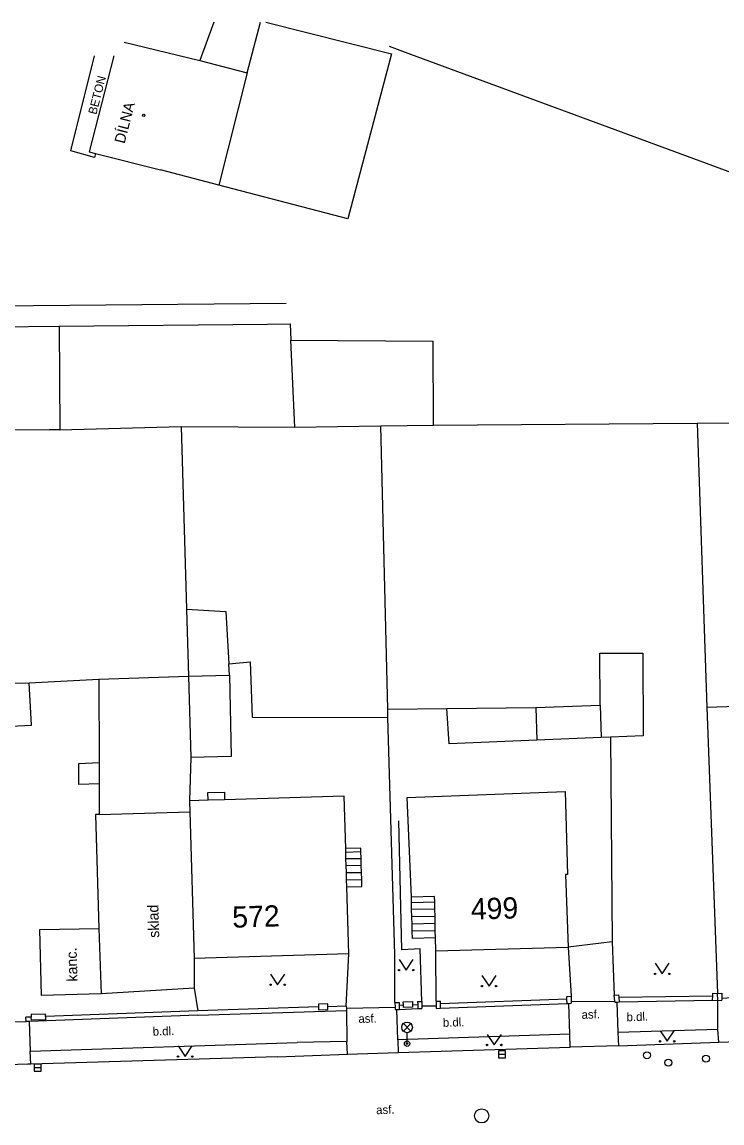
# Model space of a CAD drawing. Extents: x -642282 to -641982, y -1041678 to -1041427.
# Drawn here: x -642103.8 to -642054.4, y -1041504.2 to -1041426.5 of the extents above; entities that cross this region are included whole.
import ezdxf

# ---------------------------------------------------------------- set-up
doc = ezdxf.new("R2010")
doc.units = 0
for name, color, linetype in [('Budovy', 7, 'Continuous'), ('Ploty', 7, 'Continuous'), ('Popis objektů', 7, 'Continuous'), ('Popis povrchů', 7, 'Continuous'), ('Popis ČP_ ČE', 7, 'Continuous'), ('Pris-HUP', 7, 'Continuous'), ('Rozhraní ploch 1', 7, 'Continuous'), ('Rozhraní ploch 2', 7, 'Continuous'), ('Vstup na pozemky', 7, 'Continuous'), ('Znaky doprava', 7, 'Continuous'), ('Znaky kanalizace', 7, 'Continuous'), ('Znaky voda', 7, 'Continuous'), ('Značky KM', 7, 'Continuous'), ('Značky předmětů', 7, 'Continuous')]:
    doc.layers.add(name, color=color, linetype=linetype)

msp = doc.modelspace()

# ---------------------------------------------------------------- linework, layer by layer
at = {"layer": 'Budovy'}
for p, q in [((-642087.9, -1041430.08), (-642086.974, -1041426.503)), ((-642086.585, -1041426.503), (-642077.74, -1041428.76)), ((-642096.59, -1041427.92), (-642091.24, -1041429.22)), ((-642097.312, -1041428.899), (-642099.05, -1041435.67)), ((-642077.74, -1041428.76), (-642080.82, -1041440.39)), ((-642091.24, -1041429.22), (-642087.9, -1041430.08)), ((-642087.9, -1041430.08), (-642089.91, -1041438.01)), ((-642099.05, -1041435.67), (-642098.61, -1041435.79)), ((-642098.61, -1041435.79), (-642094.03, -1041436.93)), ((-642089.91, -1041438.01), (-642094.03, -1041436.93)), ((-642080.82, -1041440.39), (-642089.91, -1041438.01)), ((-642133.96, -1041448.34), (-642101.16, -1041447.981)), ((-642101.16, -1041447.981), (-642086.48, -1041447.82)), ((-642101.16, -1041447.981), (-642101.12, -1041455.28)), ((-642086.48, -1041447.82), (-642084.88, -1041447.8)), ((-642084.88, -1041447.8), (-642084.826, -1041448.968)), ((-642084.54, -1041455.11), (-642084.826, -1041448.968)), ((-642101.88, -1041455.29), (-642108.5, -1041455.35)), ((-642101.12, -1041455.28), (-642101.88, -1041455.29)), ((-642101.12, -1041455.28), (-642092.57, -1041455.06)), ((-642092.57, -1041455.06), (-642084.54, -1041455.11)), ((-642092.57, -1041455.06), (-642092.19, -1041467.96)), ((-642092.19, -1041467.96), (-642092.05, -1041472.69)), ((-642092.19, -1041467.96), (-642089.42, -1041468.11)), ((-642089.42, -1041468.11), (-642089.21, -1041471.8)), ((-642063.02, -1041474.73), (-642063.03, -1041471.05)), ((-642063.03, -1041471.05), (-642060, -1041471.05)), ((-642060, -1041471.05), (-642059.98, -1041476.89)), ((-642089.16, -1041472.6), (-642089.21, -1041471.8)), ((-642108.03, -1041473.19), (-642103.28, -1041473.15)), ((-642103.28, -1041473.15), (-642098.38, -1041472.9)), ((-642103.13, -1041476.14), (-642103.28, -1041473.15)), ((-642098.38, -1041472.9), (-642092.05, -1041472.69)), ((-642098.38, -1041472.9), (-642098.36, -1041478.78)), ((-642092.05, -1041472.69), (-642089.16, -1041472.6)), ((-642092.05, -1041472.69), (-642091.88, -1041478.41)), ((-642089.16, -1041472.6), (-642089.05, -1041478.36)), ((-642067.54, -1041474.88), (-642063.02, -1041474.73)), ((-642063.02, -1041474.73), (-642062.94, -1041477.01)), ((-642067.54, -1041474.88), (-642067.47, -1041477.2)), ((-642107.945, -1041476.383), (-642103.13, -1041476.14)), ((-642062.94, -1041477.01), (-642067.47, -1041477.2)), ((-642062.28, -1041476.98), (-642062.94, -1041477.01)), ((-642059.98, -1041476.89), (-642062.28, -1041476.98)), ((-642091.88, -1041478.41), (-642091.97, -1041481.48)), ((-642089.05, -1041478.36), (-642091.88, -1041478.41)), ((-642099.79, -1041478.85), (-642098.36, -1041478.78)), ((-642099.79, -1041480.33), (-642099.79, -1041478.85)), ((-642098.36, -1041478.78), (-642098.36, -1041480.28)), ((-642098.36, -1041480.28), (-642099.79, -1041480.33)), ((-642098.36, -1041480.28), (-642098.35, -1041482.45)), ((-642076.63, -1041481.25), (-642065.47, -1041480.82)), ((-642065.47, -1041480.82), (-642065.31, -1041486.68)), ((-642090.669, -1041481.442), (-642091.97, -1041481.48)), ((-642091.97, -1041481.48), (-642091.95, -1041482.26)), ((-642089.509, -1041481.408), (-642090.669, -1041481.442)), ((-642081.07, -1041481.16), (-642089.509, -1041481.408)), ((-642080.96, -1041484.85), (-642081.07, -1041481.16)), ((-642076.33, -1041488.27), (-642076.63, -1041481.25)), ((-642098.35, -1041482.45), (-642098.6, -1041482.45)), ((-642098.6, -1041482.45), (-642098.37, -1041490.49)), ((-642098.35, -1041482.45), (-642091.95, -1041482.26)), ((-642091.95, -1041482.26), (-642091.64, -1041492.62)), ((-642080.95, -1041485.11), (-642080.96, -1041484.85)), ((-642080.94, -1041485.54), (-642080.95, -1041485.11)), ((-642080.93, -1041486.04), (-642080.94, -1041485.54)), ((-642080.91, -1041486.55), (-642080.93, -1041486.04)), ((-642080.9, -1041487.06), (-642080.91, -1041486.55)), ((-642080.88, -1041487.56), (-642080.9, -1041487.06)), ((-642065.31, -1041486.68), (-642065.46, -1041486.69)), ((-642065.46, -1041486.69), (-642065.27, -1041491.82)), ((-642080.74, -1041492.29), (-642080.88, -1041487.56)), ((-642074.69, -1041488.23), (-642076.33, -1041488.27)), ((-642074.68, -1041488.64), (-642074.69, -1041488.23)), ((-642074.67, -1041489.13), (-642074.68, -1041488.64)), ((-642074.66, -1041489.64), (-642074.67, -1041489.13)), ((-642074.65, -1041490.14), (-642074.66, -1041489.64)), ((-642074.64, -1041490.65), (-642074.65, -1041490.14)), ((-642102.53, -1041490.57), (-642098.37, -1041490.49)), ((-642102.42, -1041495.22), (-642102.53, -1041490.57)), ((-642098.37, -1041490.49), (-642098.22, -1041495.1)), ((-642074.62, -1041491.16), (-642074.64, -1041490.65)), ((-642074.6, -1041492.06), (-642074.62, -1041491.16)), ((-642074.6, -1041492.06), (-642065.27, -1041491.82)), ((-642080.74, -1041492.29), (-642091.64, -1041492.62)), ((-642091.64, -1041492.62), (-642091.64, -1041494.7)), ((-642091.64, -1041494.7), (-642098.22, -1041495.1)), ((-642098.22, -1041495.1), (-642102.42, -1041495.22))]:
    msp.add_line(p, q, dxfattribs=at)
at = {"layer": 'Ploty'}
for p, q in [((-642055.49, -1041474.87), (-642054.73, -1041495.07)), ((-642077.5, -1041492.32), (-642077.98, -1041475.6)), ((-642080.919, -1041495.97), (-642080.74, -1041492.29)), ((-642077.487, -1041495.72), (-642077.5, -1041492.32)), ((-642091.64, -1041494.7), (-642091.391, -1041496.3)), ((-642076.26, -1041495.88), (-642075.88, -1041495.85)), ((-642075.887, -1041495.65), (-642075.88, -1041495.85)), ((-642075.88, -1041495.85), (-642075.87, -1041496.15)), ((-642065.36, -1041495.48), (-642074.278, -1041495.82)), ((-642074.27, -1041496.12), (-642065.35, -1041495.78)), ((-642055.072, -1041495.26), (-642061.689, -1041495.37)), ((-642061.66, -1041495.67), (-642055.08, -1041495.56)), ((-642091.38, -1041496.6), (-642103.29, -1041497.052)), ((-642091.391, -1041496.3), (-642102.142, -1041496.708)), ((-642082.872, -1041496.032), (-642091.391, -1041496.3)), ((-642091.38, -1041496.6), (-642080.91, -1041496.27)), ((-642080.919, -1041495.97), (-642082.223, -1041496.011)), ((-642077.19, -1041495.91), (-642076.88, -1041495.89)), ((-642077.18, -1041496.21), (-642075.87, -1041496.15)), ((-642103.14, -1041496.746), (-642103.511, -1041496.76)), ((-642103.5, -1041497.06), (-642103.511, -1041496.76)), ((-642103.29, -1041497.052), (-642103.5, -1041497.06))]:
    msp.add_line(p, q, dxfattribs=at)
for points in [[(-642077.197, -1041495.71), (-642077.19, -1041495.91), (-642077.18, -1041496.21)], [(-642080.919, -1041495.97), (-642080.915, -1041496.107), (-642080.91, -1041496.27)]]:
    msp.add_lwpolyline(points, dxfattribs=at)
at = {"layer": 'Pris-HUP'}
for points in [[(-642082.223, -1041496.011), (-642082.226, -1041495.816), (-642082.876, -1041495.828), (-642082.872, -1041496.032)], [(-642076.26, -1041495.88), (-642076.238, -1041496.036), (-642076.887, -1041496.069), (-642076.88, -1041495.89), (-642076.907, -1041495.67), (-642076.258, -1041495.637), (-642076.26, -1041495.88)], [(-642102.142, -1041496.708), (-642102.147, -1041496.541), (-642103.146, -1041496.574), (-642103.14, -1041496.746)], [(-642082.872, -1041496.032), (-642082.869, -1041496.228), (-642082.219, -1041496.216), (-642082.223, -1041496.011)], [(-642102.142, -1041496.708), (-642102.134, -1041496.941), (-642103.133, -1041496.974), (-642103.14, -1041496.746)]]:
    msp.add_lwpolyline(points, dxfattribs=at)
at = {"layer": 'Rozhraní ploch 1'}
for p, q in [((-642100.36, -1041435.6), (-642098.67, -1041428.899)), ((-642133.74, -1041446.78), (-642085.16, -1041446.36)), ((-642077.01, -1041491.99), (-642077.21, -1041482.89)), ((-642080.95, -1041485.11), (-642079.89, -1041485.06)), ((-642080.94, -1041485.54), (-642079.88, -1041485.54)), ((-642079.88, -1041485.54), (-642079.89, -1041485.06)), ((-642079.86, -1041486.02), (-642079.88, -1041485.54)), ((-642080.93, -1041486.04), (-642079.86, -1041486.02)), ((-642080.91, -1041486.55), (-642079.85, -1041486.53)), ((-642079.85, -1041486.53), (-642079.86, -1041486.02)), ((-642079.83, -1041487.04), (-642079.85, -1041486.53)), ((-642080.9, -1041487.06), (-642079.83, -1041487.04)), ((-642076.32, -1041488.67), (-642076.33, -1041488.27)), ((-642074.68, -1041488.64), (-642076.32, -1041488.67)), ((-642076.31, -1041489.16), (-642076.32, -1041488.67)), ((-642074.67, -1041489.13), (-642076.31, -1041489.16)), ((-642076.3, -1041489.67), (-642076.31, -1041489.16)), ((-642074.66, -1041489.64), (-642076.3, -1041489.67)), ((-642076.28, -1041490.18), (-642076.3, -1041489.67)), ((-642074.65, -1041490.14), (-642076.28, -1041490.18)), ((-642076.27, -1041490.69), (-642076.28, -1041490.18)), ((-642074.64, -1041490.65), (-642076.27, -1041490.69)), ((-642065.27, -1041491.82), (-642065.067, -1041495.27)), ((-642062.17, -1041491.43), (-642062.018, -1041495.202)), ((-642074.581, -1041495.628), (-642074.6, -1041492.06)), ((-642065.14, -1041497.95), (-642077.29, -1041498.35)), ((-642065.13, -1041498.87), (-642065.14, -1041497.95)), ((-642054.71, -1041497.63), (-642061.76, -1041497.84)), ((-642061.76, -1041497.84), (-642061.71, -1041498.77)), ((-642054.64, -1041498.51), (-642054.71, -1041497.63)), ((-642103.21, -1041499.16), (-642084.387, -1041498.543)), ((-642080.87, -1041498.47), (-642084.387, -1041498.543)), ((-642080.84, -1041499.36), (-642080.87, -1041498.47)), ((-642077.29, -1041498.35), (-642077.27, -1041499.25)), ((-642077.27, -1041499.25), (-642065.13, -1041498.87)), ((-642061.71, -1041498.77), (-642065.13, -1041498.87)), ((-642061.71, -1041498.77), (-642054.64, -1041498.51)), ((-642054.64, -1041498.51), (-642050.19, -1041498.38)), ((-642103.179, -1041500.063), (-642103.21, -1041499.16)), ((-642085.76, -1041499.56), (-642103.179, -1041500.063)), ((-642085.76, -1041499.56), (-642080.84, -1041499.36)), ((-642080.84, -1041499.36), (-642077.27, -1041499.25)), ((-642103.379, -1041500.069), (-642107.27, -1041500.182)), ((-642103.179, -1041500.063), (-642103.379, -1041500.069))]:
    msp.add_line(p, q, dxfattribs=at)
for points in [[(-642098.61, -1041435.79), (-642098.68, -1041436.06), (-642100.36, -1041435.6)], [(-642079.89, -1041485.06), (-642079.9, -1041484.81), (-642080.96, -1041484.85)], [(-642080.88, -1041487.56), (-642079.82, -1041487.53), (-642079.83, -1041487.04)], [(-642074.62, -1041491.16), (-642076.26, -1041491.2), (-642076.27, -1041490.69)], [(-642075.597, -1041495.64), (-642075.71, -1041491.93), (-642077.01, -1041491.99)]]:
    msp.add_lwpolyline(points, dxfattribs=at)
at = {"layer": 'Rozhraní ploch 2'}
for p, q in [((-642090.255, -1041426.503), (-642091.24, -1041429.22)), ((-642077.89, -1041428.21), (-642076.4, -1041428.78)), ((-642076.4, -1041428.78), (-642052.34, -1041437.66)), ((-642084.826, -1041448.968), (-642074.78, -1041449.03)), ((-642074.76, -1041454.97), (-642074.78, -1041449.03)), ((-642084.54, -1041455.11), (-642078.49, -1041455.01)), ((-642078.49, -1041455.01), (-642074.76, -1041454.97)), ((-642077.99, -1041475.02), (-642078.49, -1041455.01)), ((-642074.76, -1041454.97), (-642056.17, -1041454.82)), ((-642056.17, -1041454.82), (-642052.16, -1041454.78)), ((-642056.17, -1041454.82), (-642055.49, -1041474.87)), ((-642089.21, -1041471.8), (-642087.71, -1041471.67)), ((-642087.71, -1041471.67), (-642087.56, -1041475.58)), ((-642055.49, -1041474.87), (-642042.21, -1041474.43)), ((-642087.56, -1041475.58), (-642077.98, -1041475.6)), ((-642077.99, -1041475.02), (-642073.82, -1041474.96)), ((-642077.98, -1041475.6), (-642077.99, -1041475.02)), ((-642073.82, -1041474.96), (-642067.54, -1041474.88)), ((-642073.66, -1041477.45), (-642073.82, -1041474.96)), ((-642067.47, -1041477.2), (-642073.66, -1041477.45)), ((-642062.28, -1041476.98), (-642062.17, -1041491.43)), ((-642090.68, -1041480.9), (-642089.52, -1041480.87)), ((-642090.669, -1041481.442), (-642090.68, -1041480.9)), ((-642089.52, -1041480.87), (-642089.509, -1041481.408)), ((-642062.17, -1041491.43), (-642065.27, -1041491.82)), ((-642055.066, -1041495.06), (-642054.73, -1041495.07)), ((-642054.73, -1041495.07), (-642054.439, -1041495.064)), ((-642054.72, -1041495.57), (-642054.73, -1041495.07)), ((-642077.487, -1041495.72), (-642077.197, -1041495.71)), ((-642075.887, -1041495.65), (-642075.597, -1041495.64)), ((-642074.581, -1041495.628), (-642074.283, -1041495.62)), ((-642065.367, -1041495.28), (-642065.067, -1041495.27)), ((-642065.14, -1041497.95), (-642065.215, -1041495.775)), ((-642062.018, -1041495.202), (-642061.708, -1041495.172)), ((-642061.846, -1041495.688), (-642061.76, -1041497.84)), ((-642055.08, -1041495.56), (-642054.72, -1041495.57)), ((-642054.72, -1041495.57), (-642054.43, -1041495.54)), ((-642054.71, -1041497.63), (-642054.72, -1041495.57)), ((-642080.91, -1041496.27), (-642080.87, -1041498.47)), ((-642077.29, -1041498.35), (-642077.361, -1041496.216)), ((-642075.87, -1041496.15), (-642075.58, -1041496.14)), ((-642074.57, -1041496.13), (-642074.27, -1041496.12)), ((-642103.29, -1041497.052), (-642103.21, -1041499.16))]:
    msp.add_line(p, q, dxfattribs=at)
for points in [[(-642055.08, -1041495.56), (-642055.072, -1041495.26), (-642055.066, -1041495.06)], [(-642054.439, -1041495.064), (-642054.432, -1041495.407), (-642054.43, -1041495.54)], [(-642077.487, -1041495.72), (-642077.476, -1041496.037), (-642077.47, -1041496.22)], [(-642075.597, -1041495.64), (-642075.586, -1041495.97), (-642075.58, -1041496.14)], [(-642074.581, -1041495.628), (-642074.572, -1041495.97), (-642074.57, -1041496.13)], [(-642074.27, -1041496.12), (-642074.278, -1041495.82), (-642074.283, -1041495.62)], [(-642065.35, -1041495.78), (-642065.36, -1041495.48), (-642065.367, -1041495.28)], [(-642065.35, -1041495.78), (-642065.215, -1041495.775), (-642065.05, -1041495.77)], [(-642065.067, -1041495.27), (-642065.054, -1041495.655), (-642065.05, -1041495.77)], [(-642061.97, -1041495.7), (-642061.977, -1041495.625), (-642062.018, -1041495.202)], [(-642061.97, -1041495.7), (-642061.846, -1041495.688), (-642061.66, -1041495.67)], [(-642061.708, -1041495.172), (-642061.689, -1041495.37), (-642061.66, -1041495.67)], [(-642077.47, -1041496.22), (-642077.361, -1041496.216), (-642077.18, -1041496.21)]]:
    msp.add_lwpolyline(points, dxfattribs=at)
at = {"layer": 'Vstup na pozemky'}
for p, q in [((-642065.054, -1041495.655), (-642061.977, -1041495.625)), ((-642054.432, -1041495.407), (-642051.781, -1041495.233)), ((-642080.915, -1041496.107), (-642077.476, -1041496.037)), ((-642074.572, -1041495.97), (-642075.586, -1041495.97)), ((-642107.34, -1041497.12), (-642103.5, -1041497.06))]:
    msp.add_line(p, q, dxfattribs=at)
at = {"layer": 'Znaky doprava'}
for p, q in [((-642076.895, -1041497.205), (-642076.365, -1041497.735)), ((-642076.895, -1041497.735), (-642076.365, -1041497.205)), ((-642076.63, -1041498.62), (-642076.63, -1041497.845))]:
    msp.add_line(p, q, dxfattribs=at)
for centre, radius in [((-642076.63, -1041497.47), 0.375), ((-642076.63, -1041498.62), 0.19), ((-642076.63, -1041498.62), 0.05)]:
    msp.add_circle(centre, radius, dxfattribs=at)
at = {"layer": 'Znaky kanalizace'}
for p, q in [((-642070.18, -1041499.37), (-642069.68, -1041499.37)), ((-642102.93, -1041500.31), (-642102.43, -1041500.31))]:
    msp.add_line(p, q, dxfattribs=at)
for points in [[(-642070.18, -1041499.62), (-642069.68, -1041499.62), (-642069.68, -1041499.12), (-642070.18, -1041499.12)], [(-642102.93, -1041500.56), (-642102.43, -1041500.56), (-642102.43, -1041500.06), (-642102.93, -1041500.06)]]:
    msp.add_lwpolyline(points, close=True, dxfattribs=at)
msp.add_circle((-642071.37, -1041503.72), 0.5, dxfattribs=at)
at = {"layer": 'Znaky voda'}
for centre in [(-642059.71, -1041499.44), (-642058.2, -1041499.96), (-642055.55, -1041499.68)]:
    msp.add_circle(centre, 0.25, dxfattribs=at)
at = {"layer": 'Značky KM'}
for p, q in [((-642077.2, -1041492.68), (-642076.7, -1041493.43)), ((-642076.7, -1041493.43), (-642076.2, -1041492.68)), ((-642059.14, -1041492.95), (-642058.64, -1041493.7)), ((-642058.64, -1041493.7), (-642058.14, -1041492.95)), ((-642086.26, -1041493.71), (-642085.76, -1041494.46)), ((-642085.76, -1041494.46), (-642085.26, -1041493.71)), ((-642071.35, -1041493.81), (-642070.85, -1041494.56)), ((-642070.85, -1041494.56), (-642070.35, -1041493.81)), ((-642070.982, -1041497.964), (-642070.482, -1041498.714)), ((-642070.482, -1041498.714), (-642069.982, -1041497.964)), ((-642058.785, -1041497.706), (-642058.285, -1041498.456)), ((-642058.285, -1041498.456), (-642057.785, -1041497.706)), ((-642092.789, -1041498.784), (-642092.289, -1041499.534)), ((-642092.289, -1041499.534), (-642091.789, -1041498.784))]:
    msp.add_line(p, q, dxfattribs=at)
for centre in [(-642077.2, -1041493.43), (-642076.2, -1041493.43), (-642059.14, -1041493.7), (-642058.14, -1041493.7), (-642086.26, -1041494.46), (-642085.26, -1041494.46), (-642071.35, -1041494.56), (-642070.35, -1041494.56), (-642070.982, -1041498.714), (-642069.982, -1041498.714), (-642058.785, -1041498.456), (-642057.785, -1041498.456), (-642092.789, -1041499.535), (-642091.789, -1041499.535)]:
    msp.add_circle(centre, 0.05, dxfattribs=at)
at = {"layer": 'Značky předmětů'}
msp.add_circle((-642095.21, -1041433.09), 0.0875, dxfattribs=at)

# ---------------------------------------------------------------- texts
at = {"layer": 'Popis objektů'}
for s, rotation, p in [('DÍLNA', 75.6165, (-642096.56, -1041435.13)), ('sklad', 91.6586, (-642094.111, -1041491.14)), ('kanc.', 91.7847, (-642099.867, -1041494.228))]:
    msp.add_text(s, height=0.75, rotation=rotation, dxfattribs=at).set_placement(p)
at = {"layer": 'Popis povrchů'}
for s, rotation, p in [('BETON', 75.6165, (-642098.55, -1041433.07)), ('asf.', 1.66348, (-642080.056, -1041497.163)), ('asf.', 1.66348, (-642064.314, -1041496.871)), ('b.dl.', 1.8434, (-642061.139, -1041497.043)), ('b.dl.', 1.8434, (-642094.565, -1041498.061)), ('b.dl.', 1.8434, (-642074.097, -1041497.436)), ('asf.', 1.81713, (-642078.802, -1041503.602))]:
    msp.add_text(s, height=0.6, rotation=rotation, dxfattribs=at).set_placement(p)
at = {"layer": 'Popis ČP_ ČE'}
for s, rotation, p in [(' 572', 1.7355, (-642089.499, -1041490.458)), ('499', 1.59454, (-642072.117, -1041489.868))]:
    msp.add_text(s, height=1.5, rotation=rotation, dxfattribs=at).set_placement(p)

doc.saveas('drawing.dxf')
